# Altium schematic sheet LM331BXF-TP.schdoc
size 127 x 101 mm
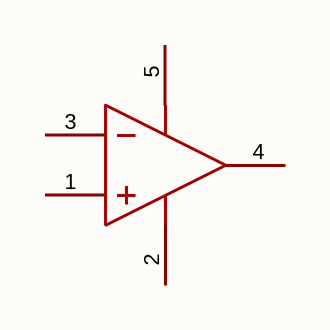
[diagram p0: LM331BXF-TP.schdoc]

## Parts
U?  lm331bxf-tp  [SOT-23-5_L2.9-W1.6-P0.95-LS2.8-BL]  (value not drawn)

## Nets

Not connected (* = marked no-connect by the designer): U? 1(+IN) 2(V-) 3(-IN) 4(OUT) 5(V+)

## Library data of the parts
U? = lm331bxf-tp: 比较器数:1;输入失调电压(Vos):1mV;输入偏置电流(Ib):25nA;; Manufacturer: TECH PUBLIC(台舟); AddInBom: yes; ModelId: 018c57e721114987ae90467fe9f1d259; ModelTransform: 114.96,110.236,0,0,0,0,0,0,0; Number of Channels: 1; Vos - Input Offset Voltage: 1mV; Ib - Input Bias Current: 25nA; Output Type: 开路漏极; Quiescent Current: 400uA; Single Supply: 2V~36V; Dual Supply: -18V~-1V；1V~18V; Input Offset Current(Ios): 5nA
